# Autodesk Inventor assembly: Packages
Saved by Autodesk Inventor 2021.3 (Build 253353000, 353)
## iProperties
Created: 2023-03
Part Number: Packages
Document SubType Name: Assembly
Designer: AdminForWorker
Title: Packages
Author: AdminForWorker
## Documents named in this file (5)
- z:\worker\convert-fusion-r08-cosv3\tmp\job-1\3553\output\files\82b4d9ad-b575-4129-b9ca-4964d6b72adf\Packages.iam
- z:\worker\convert-fusion-r08-cosv3\tmp\job-1\3553\output\files\82b4d9ad-b575-4129-b9ca-4964d6b72adf\DTF13-12PA.ipt
- z:\worker\convert-fusion-r08-cosv3\tmp\job-1\3553\output\files\82b4d9ad-b575-4129-b9ca-4964d6b72adf\WL-SMRW_1206_DOME_REV.iam
- z:\worker\convert-fusion-r08-cosv3\tmp\job-1\3553\output\files\82b4d9ad-b575-4129-b9ca-4964d6b72adf\SMB.ipt
- z:\worker\convert-fusion-r08-cosv3\tmp\job-1\3553\output\files\82b4d9ad-b575-4129-b9ca-4964d6b72adf\R1206.ipt
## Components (21 placed, 21 different names)
1. DTF13-12PA:X2
2. WL-SMRW_1206_DOME_REV:BLINKER_LINKS [sub-assembly]
3. WL-SMRW_1206_DOME_REV:BLINKER_RECHTS [sub-assembly]
4. WL-SMRW_1206_DOME_REV:LICHT_LINKS [sub-assembly]
5. WL-SMRW_1206_DOME_REV:LICHT_RECHTS [sub-assembly]
6. WL-SMRW_1206_DOME_REV:BREMSLEUCHTE [sub-assembly]
7. WL-SMRW_1206_DOME_REV:NEBELSCHLUSSLEUCHTE [sub-assembly]
8. WL-SMRW_1206_DOME_REV:STROMVERSORGUNG [sub-assembly]
9. WL-SMRW_1206_DOME_REV:LADELEITUNG [sub-assembly]
10. WL-SMRW_1206_DOME_REV:RUECKFAHRLEUCHTE [sub-assembly]
11. SMB:D1
12. SMB:D2
13. R1206:R2
14. R1206:R1
15. R1206:R3
16. R1206:R4
17. R1206:R5
18. R1206:R6
19. R1206:R7
20. R1206:R8
21. R1206:R9
